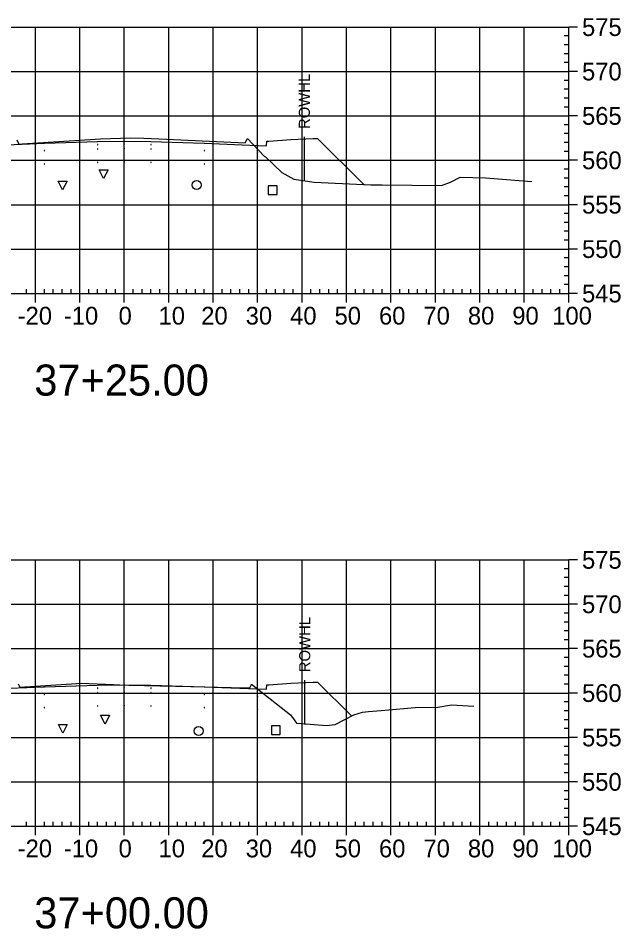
# Model space of a CAD drawing. Extents: x 708103 to 717568, y 374476 to 378707.
# Drawn here: x 711228.1 to 711363.7, y 377111.5 to 377316.6 of the extents above; entities that cross this region are included whole.
import ezdxf

# ---------------------------------------------------------------- set-up
doc = ezdxf.new("R2010")
doc.units = 0
for name, color, linetype in [('1', 7, 'Continuous'), ('13', 7, 'Continuous'), ('14', 7, 'Continuous'), ('22', 7, 'Continuous'), ('4', 7, 'Continuous'), ('57', 7, 'Continuous'), ('Existing', 7, 'Continuous'), ('XS_Right_of_Way', 7, 'Continuous')]:
    doc.layers.add(name, color=color, linetype=linetype)

msp = doc.modelspace()

# ---------------------------------------------------------------- linework, layer by layer
for points in [[(711233.93, 377286.76), (711234.03, 377286.76), (711234.03, 377286.86), (711233.93, 377286.86)], [(711245.93, 377288.12), (711246.03, 377288.12), (711246.03, 377288.22), (711245.93, 377288.22)], [(711245.93, 377287.12), (711246.03, 377287.12), (711246.03, 377287.22), (711245.93, 377287.22)], [(711251.93, 377288.24), (711252.03, 377288.24), (711252.03, 377288.34), (711251.93, 377288.34)], [(711251.93, 377287.24), (711252.03, 377287.24), (711252.03, 377287.34), (711251.93, 377287.34)], [(711257.93, 377288.12), (711258.03, 377288.12), (711258.03, 377288.22), (711257.93, 377288.22)], [(711257.93, 377287.12), (711258.03, 377287.12), (711258.03, 377287.22), (711257.93, 377287.22)], [(711269.93, 377286.76), (711270.03, 377286.76), (711270.03, 377286.86), (711269.93, 377286.86)], [(711281.93, 377286.28), (711282.03, 377286.28), (711282.03, 377286.38), (711281.93, 377286.38)], [(711233.93, 377283.76), (711234.03, 377283.76), (711234.03, 377283.86), (711233.93, 377283.86)], [(711245.93, 377284.12), (711246.03, 377284.12), (711246.03, 377284.22), (711245.93, 377284.22)], [(711251.93, 377284.24), (711252.03, 377284.24), (711252.03, 377284.34), (711251.93, 377284.34)], [(711257.93, 377284.12), (711258.03, 377284.12), (711258.03, 377284.22), (711257.93, 377284.22)], [(711269.93, 377283.76), (711270.03, 377283.76), (711270.03, 377283.86), (711269.93, 377283.86)], [(711281.93, 377283.28), (711282.03, 377283.28), (711282.03, 377283.38), (711281.93, 377283.38)], [(711245.93, 377165.67), (711246.03, 377165.67), (711246.03, 377165.77), (711245.93, 377165.77)], [(711251.93, 377165.79), (711252.03, 377165.79), (711252.03, 377165.89), (711251.93, 377165.89)], [(711257.93, 377165.67), (711258.03, 377165.67), (711258.03, 377165.77), (711257.93, 377165.77)], [(711233.93, 377164.31), (711234.03, 377164.31), (711234.03, 377164.41), (711233.93, 377164.41)], [(711245.93, 377164.67), (711246.03, 377164.67), (711246.03, 377164.77), (711245.93, 377164.77)], [(711251.93, 377164.79), (711252.03, 377164.79), (711252.03, 377164.89), (711251.93, 377164.89)], [(711257.93, 377164.67), (711258.03, 377164.67), (711258.03, 377164.77), (711257.93, 377164.77)], [(711269.93, 377164.31), (711270.03, 377164.31), (711270.03, 377164.41), (711269.93, 377164.41)], [(711281.93, 377163.83), (711282.03, 377163.83), (711282.03, 377163.93), (711281.93, 377163.93)], [(711233.93, 377161.31), (711234.03, 377161.31), (711234.03, 377161.41), (711233.93, 377161.41)], [(711245.93, 377161.67), (711246.03, 377161.67), (711246.03, 377161.77), (711245.93, 377161.77)], [(711251.93, 377161.79), (711252.03, 377161.79), (711252.03, 377161.89), (711251.93, 377161.89)], [(711257.93, 377161.67), (711258.03, 377161.67), (711258.03, 377161.77), (711257.93, 377161.77)], [(711269.93, 377161.31), (711270.03, 377161.31), (711270.03, 377161.41), (711269.93, 377161.41)], [(711281.93, 377160.83), (711282.03, 377160.83), (711282.03, 377160.93), (711281.93, 377160.93)]]:
    msp.add_lwpolyline(points, close=True)
at = {"layer": '1'}
for points in [[(711247.32, 377280.51), (711246.32, 377282.51), (711248.32, 377282.51)], [(711238.08, 377277.94), (711237.08, 377279.94), (711239.08, 377279.94)], [(711247.65, 377157.66), (711246.65, 377159.66), (711248.65, 377159.66)], [(711238.14, 377155.58), (711237.14, 377157.58), (711239.14, 377157.58)]]:
    msp.add_lwpolyline(points, close=True, dxfattribs=at)
at = {"layer": '13'}
for centre in [(711268.26, 377279.06), (711268.71, 377156.09)]:
    msp.add_circle(centre, 1, dxfattribs=at)
at = {"layer": '14'}
for points in [[(711233.98, 377288.47), (711233.98, 377288.52), (711233.98, 377288.47), (711233.93, 377288.47), (711233.98, 377288.47), (711233.98, 377288.42), (711233.98, 377288.47), (711234.03, 377288.47)], [(711251.98, 377288.95), (711251.98, 377289), (711251.98, 377288.95), (711251.93, 377288.95), (711251.98, 377288.95), (711251.98, 377288.9), (711251.98, 377288.95), (711252.03, 377288.95)], [(711269.98, 377288.47), (711269.98, 377288.52), (711269.98, 377288.47), (711269.93, 377288.47), (711269.98, 377288.47), (711269.98, 377288.42), (711269.98, 377288.47), (711270.03, 377288.47)], [(711281.98, 377287.99), (711281.98, 377288.04), (711281.98, 377287.99), (711281.93, 377287.99), (711281.98, 377287.99), (711281.98, 377287.94), (711281.98, 377287.99), (711282.03, 377287.99)], [(711305.85, 377279.18), (711305.85, 377279.23), (711305.85, 377279.18), (711305.8, 377279.18), (711305.85, 377279.18), (711305.85, 377279.13), (711305.85, 377279.18), (711305.9, 377279.18)], [(711233.98, 377166.03), (711233.98, 377166.08), (711233.98, 377166.03), (711233.93, 377166.03), (711233.98, 377166.03), (711233.98, 377165.98), (711233.98, 377166.03), (711234.03, 377166.03)], [(711251.98, 377166.51), (711251.98, 377166.56), (711251.98, 377166.51), (711251.93, 377166.51), (711251.98, 377166.51), (711251.98, 377166.46), (711251.98, 377166.51), (711252.03, 377166.51)], [(711269.98, 377166.03), (711269.98, 377166.08), (711269.98, 377166.03), (711269.93, 377166.03), (711269.98, 377166.03), (711269.98, 377165.98), (711269.98, 377166.03), (711270.03, 377166.03)], [(711281.98, 377165.55), (711281.98, 377165.6), (711281.98, 377165.55), (711281.93, 377165.55), (711281.98, 377165.55), (711281.98, 377165.5), (711281.98, 377165.55), (711282.03, 377165.55)], [(711303.12, 377159.47), (711303.12, 377159.52), (711303.12, 377159.47), (711303.07, 377159.47), (711303.12, 377159.47), (711303.12, 377159.42), (711303.12, 377159.47), (711303.17, 377159.47)]]:
    msp.add_lwpolyline(points, dxfattribs=at)
at = {"layer": '22'}
for points in [[(711201.93, 377296.11), (711208.48, 377289.55), (711209.48, 377289.51), (711214.48, 377289.31), (711219.48, 377288.91), (711219.9, 377288.91), (711219.98, 377287.91), (711221.98, 377287.99), (711233.98, 377288.47), (711245.98, 377288.83), (711251.98, 377288.95), (711257.98, 377288.83), (711269.98, 377288.47), (711281.98, 377287.99), (711283.98, 377287.91), (711284.07, 377288.91), (711284.48, 377288.91), (711289.48, 377289.31), (711294.48, 377289.51), (711295.48, 377289.55), (711305.85, 377279.18)], [(711204.8, 377170.8), (711208.48, 377167.11), (711209.48, 377167.07), (711214.48, 377166.87), (711219.48, 377166.47), (711219.9, 377166.47), (711219.98, 377165.47), (711221.98, 377165.55), (711233.98, 377166.03), (711245.98, 377166.39), (711251.98, 377166.51), (711257.98, 377166.39), (711269.98, 377166.03), (711281.98, 377165.55), (711283.98, 377165.47), (711284.07, 377166.47), (711284.48, 377166.47), (711289.48, 377166.87), (711294.48, 377167.07), (711295.48, 377167.11), (711303.12, 377159.47)]]:
    msp.add_lwpolyline(points, dxfattribs=at)
at = {"layer": '4'}
for points in [[(711284.35, 377276.9), (711286.35, 377276.9), (711286.35, 377278.9), (711284.35, 377278.9)], [(711285.08, 377155.28), (711287.08, 377155.28), (711287.08, 377157.28), (711285.08, 377157.28)]]:
    msp.add_lwpolyline(points, close=True, dxfattribs=at)
at = {"layer": '57'}
for p, q in [((711151.98, 377314.63), (711351.98, 377314.63)), ((711231.98, 377254.63), (711231.98, 377314.63)), ((711241.98, 377254.63), (711241.98, 377314.63)), ((711251.98, 377254.63), (711251.98, 377314.63)), ((711261.98, 377254.63), (711261.98, 377314.63)), ((711271.98, 377254.63), (711271.98, 377314.63)), ((711281.98, 377254.63), (711281.98, 377314.63)), ((711291.98, 377254.63), (711291.98, 377314.63)), ((711301.98, 377254.63), (711301.98, 377314.63)), ((711311.98, 377254.63), (711311.98, 377314.63)), ((711321.98, 377254.63), (711321.98, 377314.63)), ((711331.98, 377254.63), (711331.98, 377314.63)), ((711341.98, 377254.63), (711341.98, 377314.63)), ((711351.98, 377254.63), (711351.98, 377314.63)), ((711351.98, 377254.63), (711351.98, 377314.63)), ((711353.98, 377314.63), (711351.98, 377314.63)), ((711351.98, 377312.63), (711350.98, 377312.63)), ((711351.98, 377310.63), (711350.98, 377310.63)), ((711351.98, 377308.63), (711350.98, 377308.63)), ((711351.98, 377306.63), (711350.98, 377306.63)), ((711151.98, 377304.63), (711351.98, 377304.63)), ((711353.98, 377304.63), (711351.98, 377304.63)), ((711351.98, 377302.63), (711350.98, 377302.63)), ((711351.98, 377300.63), (711350.98, 377300.63)), ((711351.98, 377298.63), (711350.98, 377298.63)), ((711151.98, 377294.63), (711351.98, 377294.63)), ((711351.98, 377296.63), (711350.98, 377296.63)), ((711353.98, 377294.63), (711351.98, 377294.63)), ((711351.98, 377292.63), (711350.98, 377292.63)), ((711351.98, 377290.63), (711350.98, 377290.63)), ((711351.98, 377288.63), (711350.98, 377288.63)), ((711351.98, 377286.63), (711350.98, 377286.63)), ((711151.98, 377284.63), (711351.98, 377284.63)), ((711353.98, 377284.63), (711351.98, 377284.63)), ((711351.98, 377282.63), (711350.98, 377282.63)), ((711351.98, 377280.63), (711350.98, 377280.63)), ((711351.98, 377278.63), (711350.98, 377278.63)), ((711351.98, 377276.63), (711350.98, 377276.63)), ((711151.98, 377274.63), (711351.98, 377274.63)), ((711353.98, 377274.63), (711351.98, 377274.63)), ((711351.98, 377272.63), (711350.98, 377272.63)), ((711351.98, 377270.63), (711350.98, 377270.63)), ((711351.98, 377268.63), (711350.98, 377268.63)), ((711351.98, 377266.63), (711350.98, 377266.63)), ((711151.98, 377264.63), (711351.98, 377264.63)), ((711353.98, 377264.63), (711351.98, 377264.63)), ((711351.98, 377262.63), (711350.98, 377262.63)), ((711351.98, 377260.63), (711350.98, 377260.63)), ((711351.98, 377258.63), (711350.98, 377258.63)), ((711351.98, 377256.63), (711350.98, 377256.63)), ((711151.98, 377254.63), (711351.98, 377254.63)), ((711151.98, 377254.63), (711351.98, 377254.63)), ((711229.98, 377254.63), (711229.98, 377255.63)), ((711231.98, 377252.63), (711231.98, 377254.63)), ((711233.98, 377254.63), (711233.98, 377255.63)), ((711235.98, 377254.63), (711235.98, 377255.63)), ((711237.98, 377254.63), (711237.98, 377255.63)), ((711239.98, 377254.63), (711239.98, 377255.63)), ((711241.98, 377252.63), (711241.98, 377254.63)), ((711243.98, 377254.63), (711243.98, 377255.63)), ((711245.98, 377254.63), (711245.98, 377255.63)), ((711247.98, 377254.63), (711247.98, 377255.63)), ((711249.98, 377254.63), (711249.98, 377255.63)), ((711251.98, 377252.63), (711251.98, 377254.63)), ((711253.98, 377254.63), (711253.98, 377255.63)), ((711255.98, 377254.63), (711255.98, 377255.63)), ((711257.98, 377254.63), (711257.98, 377255.63)), ((711259.98, 377254.63), (711259.98, 377255.63)), ((711261.98, 377252.63), (711261.98, 377254.63)), ((711263.98, 377254.63), (711263.98, 377255.63)), ((711265.98, 377254.63), (711265.98, 377255.63)), ((711267.98, 377254.63), (711267.98, 377255.63)), ((711269.98, 377254.63), (711269.98, 377255.63)), ((711271.98, 377252.63), (711271.98, 377254.63)), ((711273.98, 377254.63), (711273.98, 377255.63)), ((711275.98, 377254.63), (711275.98, 377255.63)), ((711277.98, 377254.63), (711277.98, 377255.63)), ((711279.98, 377254.63), (711279.98, 377255.63)), ((711281.98, 377252.63), (711281.98, 377254.63)), ((711283.98, 377254.63), (711283.98, 377255.63)), ((711285.98, 377254.63), (711285.98, 377255.63)), ((711287.98, 377254.63), (711287.98, 377255.63)), ((711289.98, 377254.63), (711289.98, 377255.63)), ((711291.98, 377252.63), (711291.98, 377254.63)), ((711293.98, 377254.63), (711293.98, 377255.63)), ((711295.98, 377254.63), (711295.98, 377255.63)), ((711297.98, 377254.63), (711297.98, 377255.63)), ((711299.98, 377254.63), (711299.98, 377255.63)), ((711301.98, 377252.63), (711301.98, 377254.63)), ((711303.98, 377254.63), (711303.98, 377255.63)), ((711305.98, 377254.63), (711305.98, 377255.63)), ((711307.98, 377254.63), (711307.98, 377255.63)), ((711309.98, 377254.63), (711309.98, 377255.63)), ((711311.98, 377252.63), (711311.98, 377254.63)), ((711313.98, 377254.63), (711313.98, 377255.63)), ((711315.98, 377254.63), (711315.98, 377255.63)), ((711317.98, 377254.63), (711317.98, 377255.63)), ((711319.98, 377254.63), (711319.98, 377255.63)), ((711321.98, 377252.63), (711321.98, 377254.63)), ((711323.98, 377254.63), (711323.98, 377255.63)), ((711325.98, 377254.63), (711325.98, 377255.63)), ((711327.98, 377254.63), (711327.98, 377255.63)), ((711329.98, 377254.63), (711329.98, 377255.63)), ((711331.98, 377252.63), (711331.98, 377254.63)), ((711333.98, 377254.63), (711333.98, 377255.63)), ((711335.98, 377254.63), (711335.98, 377255.63)), ((711337.98, 377254.63), (711337.98, 377255.63)), ((711339.98, 377254.63), (711339.98, 377255.63)), ((711341.98, 377252.63), (711341.98, 377254.63)), ((711343.98, 377254.63), (711343.98, 377255.63)), ((711345.98, 377254.63), (711345.98, 377255.63)), ((711347.98, 377254.63), (711347.98, 377255.63)), ((711349.98, 377254.63), (711349.98, 377255.63)), ((711351.98, 377252.63), (711351.98, 377254.63)), ((711353.98, 377254.63), (711351.98, 377254.63)), ((711151.98, 377194.63), (711351.98, 377194.63)), ((711231.98, 377134.63), (711231.98, 377194.63)), ((711241.98, 377134.63), (711241.98, 377194.63)), ((711251.98, 377134.63), (711251.98, 377194.63)), ((711261.98, 377134.63), (711261.98, 377194.63)), ((711271.98, 377134.63), (711271.98, 377194.63)), ((711281.98, 377134.63), (711281.98, 377194.63)), ((711291.98, 377134.63), (711291.98, 377194.63)), ((711301.98, 377134.63), (711301.98, 377194.63)), ((711311.98, 377134.63), (711311.98, 377194.63)), ((711321.98, 377134.63), (711321.98, 377194.63)), ((711331.98, 377134.63), (711331.98, 377194.63)), ((711341.98, 377134.63), (711341.98, 377194.63)), ((711351.98, 377134.63), (711351.98, 377194.63)), ((711351.98, 377134.63), (711351.98, 377194.63)), ((711353.98, 377194.63), (711351.98, 377194.63)), ((711351.98, 377192.63), (711350.98, 377192.63)), ((711351.98, 377190.63), (711350.98, 377190.63)), ((711351.98, 377188.63), (711350.98, 377188.63)), ((711351.98, 377186.63), (711350.98, 377186.63)), ((711151.98, 377184.63), (711351.98, 377184.63)), ((711353.98, 377184.63), (711351.98, 377184.63)), ((711351.98, 377182.63), (711350.98, 377182.63)), ((711351.98, 377180.63), (711350.98, 377180.63)), ((711351.98, 377178.63), (711350.98, 377178.63)), ((711351.98, 377176.63), (711350.98, 377176.63)), ((711151.98, 377174.63), (711351.98, 377174.63)), ((711353.98, 377174.63), (711351.98, 377174.63)), ((711351.98, 377172.63), (711350.98, 377172.63)), ((711351.98, 377170.63), (711350.98, 377170.63)), ((711351.98, 377168.63), (711350.98, 377168.63)), ((711351.98, 377166.63), (711350.98, 377166.63)), ((711151.98, 377164.63), (711351.98, 377164.63)), ((711353.98, 377164.63), (711351.98, 377164.63)), ((711351.98, 377162.63), (711350.98, 377162.63)), ((711351.98, 377160.63), (711350.98, 377160.63)), ((711351.98, 377158.63), (711350.98, 377158.63)), ((711351.98, 377156.63), (711350.98, 377156.63)), ((711151.98, 377154.63), (711351.98, 377154.63)), ((711353.98, 377154.63), (711351.98, 377154.63)), ((711351.98, 377152.63), (711350.98, 377152.63)), ((711351.98, 377150.63), (711350.98, 377150.63)), ((711351.98, 377148.63), (711350.98, 377148.63)), ((711351.98, 377146.63), (711350.98, 377146.63)), ((711151.98, 377144.63), (711351.98, 377144.63)), ((711353.98, 377144.63), (711351.98, 377144.63)), ((711351.98, 377142.63), (711350.98, 377142.63)), ((711351.98, 377140.63), (711350.98, 377140.63)), ((711351.98, 377138.63), (711350.98, 377138.63)), ((711229.98, 377134.63), (711229.98, 377135.63)), ((711233.98, 377134.63), (711233.98, 377135.63)), ((711235.98, 377134.63), (711235.98, 377135.63)), ((711237.98, 377134.63), (711237.98, 377135.63)), ((711239.98, 377134.63), (711239.98, 377135.63)), ((711243.98, 377134.63), (711243.98, 377135.63)), ((711245.98, 377134.63), (711245.98, 377135.63)), ((711247.98, 377134.63), (711247.98, 377135.63)), ((711249.98, 377134.63), (711249.98, 377135.63)), ((711253.98, 377134.63), (711253.98, 377135.63)), ((711255.98, 377134.63), (711255.98, 377135.63)), ((711257.98, 377134.63), (711257.98, 377135.63)), ((711259.98, 377134.63), (711259.98, 377135.63)), ((711263.98, 377134.63), (711263.98, 377135.63)), ((711265.98, 377134.63), (711265.98, 377135.63)), ((711267.98, 377134.63), (711267.98, 377135.63)), ((711269.98, 377134.63), (711269.98, 377135.63)), ((711273.98, 377134.63), (711273.98, 377135.63)), ((711275.98, 377134.63), (711275.98, 377135.63)), ((711277.98, 377134.63), (711277.98, 377135.63)), ((711279.98, 377134.63), (711279.98, 377135.63)), ((711283.98, 377134.63), (711283.98, 377135.63)), ((711285.98, 377134.63), (711285.98, 377135.63)), ((711287.98, 377134.63), (711287.98, 377135.63)), ((711289.98, 377134.63), (711289.98, 377135.63)), ((711293.98, 377134.63), (711293.98, 377135.63)), ((711295.98, 377134.63), (711295.98, 377135.63)), ((711297.98, 377134.63), (711297.98, 377135.63)), ((711299.98, 377134.63), (711299.98, 377135.63)), ((711303.98, 377134.63), (711303.98, 377135.63)), ((711305.98, 377134.63), (711305.98, 377135.63)), ((711307.98, 377134.63), (711307.98, 377135.63)), ((711309.98, 377134.63), (711309.98, 377135.63)), ((711313.98, 377134.63), (711313.98, 377135.63)), ((711315.98, 377134.63), (711315.98, 377135.63)), ((711317.98, 377134.63), (711317.98, 377135.63)), ((711319.98, 377134.63), (711319.98, 377135.63)), ((711323.98, 377134.63), (711323.98, 377135.63)), ((711325.98, 377134.63), (711325.98, 377135.63)), ((711327.98, 377134.63), (711327.98, 377135.63)), ((711329.98, 377134.63), (711329.98, 377135.63)), ((711333.98, 377134.63), (711333.98, 377135.63)), ((711335.98, 377134.63), (711335.98, 377135.63)), ((711337.98, 377134.63), (711337.98, 377135.63)), ((711339.98, 377134.63), (711339.98, 377135.63)), ((711343.98, 377134.63), (711343.98, 377135.63)), ((711345.98, 377134.63), (711345.98, 377135.63)), ((711347.98, 377134.63), (711347.98, 377135.63)), ((711349.98, 377134.63), (711349.98, 377135.63)), ((711351.98, 377136.63), (711350.98, 377136.63)), ((711151.98, 377134.63), (711351.98, 377134.63)), ((711151.98, 377134.63), (711351.98, 377134.63)), ((711231.98, 377132.63), (711231.98, 377134.63)), ((711241.98, 377132.63), (711241.98, 377134.63)), ((711251.98, 377132.63), (711251.98, 377134.63)), ((711261.98, 377132.63), (711261.98, 377134.63)), ((711271.98, 377132.63), (711271.98, 377134.63)), ((711281.98, 377132.63), (711281.98, 377134.63)), ((711291.98, 377132.63), (711291.98, 377134.63)), ((711301.98, 377132.63), (711301.98, 377134.63)), ((711311.98, 377132.63), (711311.98, 377134.63)), ((711321.98, 377132.63), (711321.98, 377134.63)), ((711331.98, 377132.63), (711331.98, 377134.63)), ((711341.98, 377132.63), (711341.98, 377134.63)), ((711351.98, 377132.63), (711351.98, 377134.63)), ((711353.98, 377134.63), (711351.98, 377134.63))]:
    msp.add_line(p, q, dxfattribs=at)
at = {"layer": 'Existing'}
for points in [[(711227.77, 377289.23), (711228.23, 377288.3), (711228.97, 377288.35), (711246.63, 377289.49), (711253.34, 377289.66), (711256.37, 377289.58), (711261.44, 377289.37), (711279.14, 377288.57), (711279.6, 377289.41), (711279.69, 377289.55), (711283.47, 377285.58), (711283.78, 377285.42), (711287.45, 377281.86), (711290.14, 377280.36), (711294.73, 377279.74), (711305.81, 377279.19), (711307.48, 377279.12), (711310.03, 377279.09), (711323.38, 377278.97), (711325.35, 377279.71), (711327.54, 377280.8), (711333.23, 377280.69), (711343.67, 377279.87)], [(711228.09, 377166.74), (711228.44, 377165.92), (711241.19, 377166.78), (711242.29, 377166.86), (711249.52, 377166.59), (711250.95, 377166.5), (711253.02, 377166.4), (711266.91, 377166.13), (711279.06, 377165.82), (711280.26, 377165.77), (711280.57, 377166.55), (711280.6, 377166.62), (711282.67, 377164.95), (711289.38, 377159.7), (711290.18, 377158.59), (711290.7, 377157.83), (711293.83, 377157.59), (711297.49, 377157.31), (711299.41, 377157.55), (711303.66, 377159.75), (711305.55, 377160.29), (711306.93, 377160.45), (711309.81, 377160.72), (711318.25, 377161.45), (711322.05, 377161.39), (711325.62, 377161.97), (711330.63, 377161.69)]]:
    msp.add_lwpolyline(points, dxfattribs=at)
at = {"layer": 'XS_Right_of_Way'}
for p, q in [((711292.42, 377289.92), (711292.42, 377279.92)), ((711292.51, 377167.56), (711292.51, 377157.56))]:
    msp.add_line(p, q, dxfattribs=at)

# ---------------------------------------------------------------- texts
at = {"layer": '1'}
for s, p in [('37+25.00', (711231.71, 377231.63)), ('37+00.00', (711231.71, 377111.63))]:
    msp.add_text(s, height=7, dxfattribs=at).set_placement(p)
at = {"layer": '14'}
for p in [(711289.45, 377288.6), (711294.45, 377289.46), (711294.45, 377288.8), (711289.45, 377166.15), (711294.45, 377167.02), (711294.45, 377166.35)]:
    msp.add_text('+', height=0.1, dxfattribs=at).set_placement(p)
at = {"layer": '57'}
for s, p in [('575', (711354.98, 377312.63)), ('570', (711354.98, 377302.63)), ('565', (711354.98, 377292.63)), ('560', (711354.98, 377282.63)), ('555', (711354.98, 377272.63)), ('550', (711354.98, 377262.63)), ('545', (711354.98, 377252.63)), ('-20', (711227.98, 377247.63)), ('-10', (711238.37, 377247.63)), ('0', (711250.69, 377247.63)), ('10', (711259.68, 377247.63)), ('20', (711269.29, 377247.63)), ('30', (711279.29, 377247.63)), ('40', (711289.29, 377247.63)), ('50', (711299.29, 377247.63)), ('60', (711309.29, 377247.63)), ('70', (711319.29, 377247.63)), ('80', (711329.29, 377247.63)), ('90', (711339.29, 377247.63)), ('100', (711348.28, 377247.63)), ('575', (711354.98, 377192.63)), ('570', (711354.98, 377182.63)), ('565', (711354.98, 377172.63)), ('560', (711354.98, 377162.63)), ('555', (711354.98, 377152.63)), ('550', (711354.98, 377142.63)), ('545', (711354.98, 377132.63)), ('-20', (711227.98, 377127.63)), ('-10', (711238.37, 377127.63)), ('0', (711250.69, 377127.63)), ('10', (711259.68, 377127.63)), ('20', (711269.29, 377127.63)), ('30', (711279.29, 377127.63)), ('40', (711289.29, 377127.63)), ('50', (711299.29, 377127.63)), ('60', (711309.29, 377127.63)), ('70', (711319.29, 377127.63)), ('80', (711329.29, 377127.63)), ('90', (711339.29, 377127.63)), ('100', (711348.28, 377127.63))]:
    msp.add_text(s, height=4, dxfattribs=at).set_placement(p)
at = {"layer": 'XS_Right_of_Way'}
for p in [(711293.74, 377291.68), (711293.83, 377169.32)]:
    msp.add_text('ROWHL', height=2.5, rotation=90, dxfattribs=at).set_placement(p)

doc.saveas('drawing.dxf')
